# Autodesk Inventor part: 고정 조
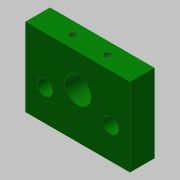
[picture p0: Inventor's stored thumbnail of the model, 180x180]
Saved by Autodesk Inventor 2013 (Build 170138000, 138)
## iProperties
Created: 2020-03
Part Number: 고정 조
Material: 알루미늄 6061
Document SubType Name: Modeling
Designer: mduedu
Density: 2.71 g/cm^3
Mass: 91.8974 g
Surface Area: 98.8495 cm^2
Volume: 33.9105 cm^3
Author: mduedu
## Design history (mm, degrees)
sketch "스케치1"
  geometry: L1 (-30, 0)-(30, 0); L2 (30, 0)-(30, 48); L3 (30, 48)-(-30, 48); L4 (-30, 48)-(-30, 0); 2 further points
  constraints: 8 end point, 2 parallel, 1 coincident, 1 horizontal, 1 midpoint, 1 perpendicular
  dimensions: "d0" = 60 distance of L1.start L1.end; "d2" = 48 distance of L1.end L2.end
extrude "돌출1" new body sketch "스케치1" distance "d3" = 14; taper "d4" = 0 deg
sketch "스케치2"
  geometry: 3 further points
  constraints: 1 horizontal alignment
  dimensions: "d5" = 7 vertical distance of point (52, 7) point (30, 0); "d6" = 22 horizontal distance of point (8, 7) point (30, 0); "d7" = 44 distance of point (52, 7) point (8, 7)
hole "구멍1" sketch "스케치2" at (8, 7), (52, 7) diameter "d8" = 3.242; stored, may be unused: countersink angle "d12" = 90 deg, drill point angle "d14" = 118 deg; dims "d9" = 8, "d10" = 4, "d11" = 2, "d13" = 10
sketch "스케치3"
  geometry: L1 (30, 0)-(-30, 0) reference; 3 further points
  constraints: 1 midpoint, 1 vertical alignment
  dimensions: "d15" = 26 distance of point (0, 0) point (0, 26)
hole "구멍2" sketch "스케치3" at (0, 26) diameter "d16" = 15; stored, may be unused: countersink angle "d20" = 90 deg, drill point angle "d22" = 118 deg; dims "d17" = 8, "d18" = 20, "d19" = 3, "d21" = 10
sketch "스케치4"
  geometry: L1 (30, 0)-(-30, 0) reference; 5 further points
  constraints: 1 coincident, 1 horizontal alignment, 1 midpoint
  dimensions: "d23" = 18 vertical distance of point (19, 18) point (0, 0); "d24" = 19 horizontal distance of point (-19, 18) point (0, 0); "d25" = 38 distance of point (19, 18) point (-19, 18)
hole "구멍7" sketch "스케치4" at (-19, 18), (19, 18) diameter "d65" = 4.5; stored, may be unused: countersink angle "d69" = 90 deg, drill point angle "d71" = 118 deg; dims "d66" = 6, "d67" = 8, "d68" = 4.4, "d70" = 8
hole "구멍8" diameter "d74" = 9; stored, may be unused: countersink angle "d78" = 90 deg, drill point angle "d80" = 0 deg; dims "d72" = 10, "d73" = 10, "d75" = 6, "d76" = 8, "d77" = 4.4, "d79" = 6
hole "구멍9" diameter "d83" = 9; stored, may be unused: countersink angle "d87" = 90 deg, drill point angle "d89" = 0 deg; dims "d81" = 10, "d82" = 10, "d84" = 6, "d85" = 8, "d86" = 4.4, "d88" = 6
sketch "스케치7"
  geometry: L1 (-18, 48)-(18, 48); L2 (18, 48)-(18, 45); L3 (18, 45)-(-18, 45); L4 (-18, 45)-(-18, 48); L5 (30, 48)-(-30, 48) reference; L6 (-30, 0)-(30, 0) reference; 5 further points
  constraints: 8 end point, 2 midpoint, 2 parallel, 1 collinear, 1 horizontal, 1 perpendicular, 1 vertical alignment
  dimensions: "d50" = 3 distance of L1.end L2.end; "d52" = 36 distance of L1.start L1.end
extrude "돌출2" cut sketch "스케치7" stored distance "d53" = 10; taper "d54" = 0 deg
sketch "스케치8"
  geometry: 3 further points
  constraints: 1 horizontal alignment
  dimensions: "d55" = 7 vertical distance of point (28, 7) point (18, 14); "d56" = 10 horizontal distance of point (8, 7) point (18, 14); "d57" = 20 distance of point (28, 7) point (8, 7)
hole "구멍6" sketch "스케치8" at (8, 7), (28, 7) diameter "d58" = 3.242; stored, may be unused: countersink angle "d62" = 90 deg, drill point angle "d64" = 118 deg; dims "d59" = 6, "d60" = 4, "d61" = 2, "d63" = 8
sketch "스케치9"
  geometry: L1 (0, 14)-(0, 0) reference; L2 (36, 0)-(0, 0) reference; L3 (48, 0)-(36, 0) reference; L4 (48, 14)-(48, 0) reference; L5 (36, 14)-(48, 14) reference; L6 (36, 0)-(36, 14) reference; L7 (0, 14)-(36, 14) reference; L8 (-12, 14)-(0, 14) reference; L9 (-12, 0)-(-12, 14) reference; L10 (0, 0)-(-12, 0) reference; C1 r 1.621 at (8, 7) reference; C2 r 1.621 at (28, 7) reference; 1 further point
extrude "돌출3" cut sketch "스케치9" stored distance "d90" = 10; taper "d91" = 0 deg
node "솔리드1"
node "절단 모서리 투영1"
